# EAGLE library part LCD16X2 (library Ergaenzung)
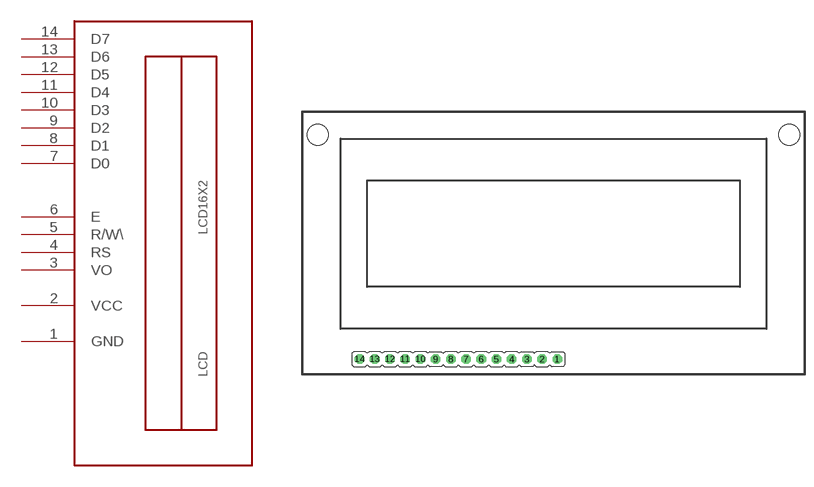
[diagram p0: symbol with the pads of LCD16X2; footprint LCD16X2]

Designator prefix LCD

## LCD16X2  [LCD16X2]
1  GND  sup
2  VCC  pwr
3  VO  in
4  RS  in
5  R/W\  in
6  E  in
7  D0
8  D1
9  D2
10  D3
11  D4
12  D5
13  D6
14  D7

## Footprint LCD16X2 (pad centres in mm)
drill 0.914 pad 1.6 octagon: 1 33.02,0; 2 30.48,0; 3 27.94,0; 4 25.4,0; 5 22.86,0; 6 20.32,0; 7 17.78,0; 8 15.24,0; 9 12.7,0; 10 10.16,0; 11 7.62,0; 12 5.08,0; 13 2.54,0; 14 0,0
hole 3.5 at -6.985,37.465
hole 3.5 at 71.755,37.465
